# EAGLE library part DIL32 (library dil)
SOCKET Dual In Line
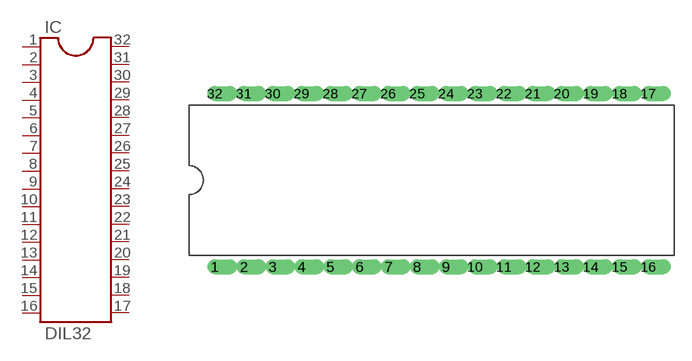
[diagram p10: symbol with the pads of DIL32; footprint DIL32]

Designator prefix IC

## DIL32  [DIL32]
1  1  pas
2  2  pas
3  3  pas
4  4  pas
5  5  pas
6  6  pas
7  7  pas
8  8  pas
9  9  pas
10  10  pas
11  11  pas
12  12  pas
13  13  pas
14  14  pas
15  15  pas
16  16  pas
17  17  pas
18  18  pas
19  19  pas
20  20  pas
21  21  pas
22  22  pas
23  23  pas
24  24  pas
25  25  pas
26  26  pas
27  27  pas
28  28  pas
29  29  pas
30  30  pas
31  31  pas
32  32  pas

## Footprint DIL32 (pad centres in mm)
SOCKET Dual In Line
drill 0.813 offset: 1 -19.05,-7.62; 2 -16.51,-7.62; 3 -13.97,-7.62; 4 -11.43,-7.62; 5 -8.89,-7.62; 6 -6.35,-7.62; 7 -3.81,-7.62; 8 -1.27,-7.62; 9 1.27,-7.62; 10 3.81,-7.62; 11 6.35,-7.62; 12 8.89,-7.62; 13 11.43,-7.62; 14 13.97,-7.62; 15 16.51,-7.62; 16 19.05,-7.62; 17 19.05,7.62; 18 16.51,7.62; 19 13.97,7.62; 20 11.43,7.62; 21 8.89,7.62; 22 6.35,7.62; 23 3.81,7.62; 24 1.27,7.62; 25 -1.27,7.62; 26 -3.81,7.62; 27 -6.35,7.62; 28 -8.89,7.62; 29 -11.43,7.62; 30 -13.97,7.62; 31 -16.51,7.62; 32 -19.05,7.62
